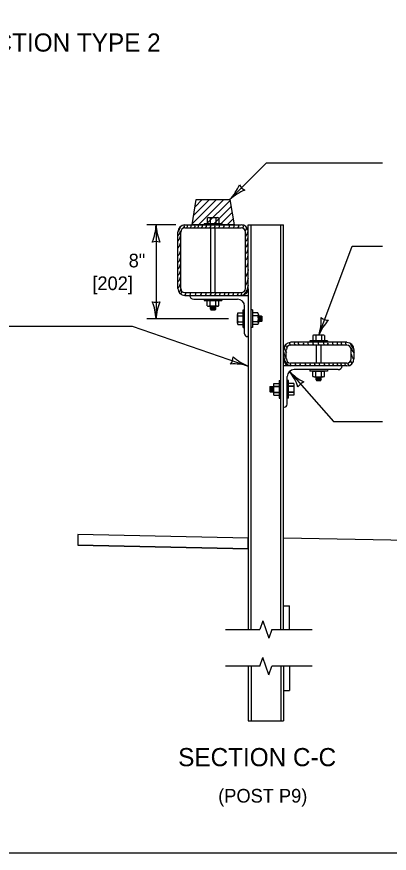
# Model space of a CAD drawing. Extents: x 49991.4 to 50021, y 49987.6 to 50011.4.
# Drawn here: x 50007.949 to 50009.589, y 49987.799 to 49991.481 of the extents above; entities that cross this region are included whole.
import ezdxf

# ---------------------------------------------------------------- set-up
doc = ezdxf.new("R2010")
doc.units = 0
for name, color, linetype in [('Level 1', 7, 'Continuous'), ('Level 2', 7, 'Continuous'), ('Level 3', 7, 'Continuous'), ('Level 4', 7, 'Continuous'), ('Level 6', 7, 'Continuous')]:
    doc.layers.add(name, color=color, linetype=linetype)

msp = doc.modelspace()

# ---------------------------------------------------------------- linework, layer by layer
at = {"layer": 'Level 1'}
for p, q in [((50008.7205, 49990.5649), (50008.739, 49990.6759)), ((50008.7212, 49990.5688), (50008.8285, 49990.6759)), ((50008.7274, 49990.6066), (50008.7969, 49990.6759)), ((50008.7338, 49990.6443), (50008.7655, 49990.6759)), ((50008.739, 49990.6759), (50008.8872, 49990.6759)), ((50008.7486, 49990.5649), (50008.8597, 49990.6759)), ((50008.7799, 49990.5649), (50008.8876, 49990.6726)), ((50008.8872, 49990.6759), (50008.9056, 49990.5649)), ((50008.8115, 49990.5649), (50008.8922, 49990.6457)), ((50008.8429, 49990.5649), (50008.8968, 49990.6188)), ((50008.8744, 49990.5649), (50008.9013, 49990.5917)), ((50008.6888, 49990.5643), (50008.6891, 49990.5649)), ((50008.689, 49990.5519), (50008.6891, 49990.552)), ((50008.6891, 49990.5649), (50008.9371, 49990.5649)), ((50008.6891, 49990.552), (50008.9371, 49990.552)), ((50008.9056, 49990.5649), (50008.7205, 49990.5649)), ((50008.8036, 49990.2665), (50008.8036, 49990.552)), ((50008.8063, 49990.552), (50008.8189, 49990.552)), ((50008.8226, 49990.2665), (50008.8226, 49990.552)), ((50008.9678, 49990.2835), (50008.9678, 49990.5649)), ((50008.9678, 49990.5649), (50009.1231, 49990.5649)), ((50008.9804, 49988.7839), (50008.9804, 49990.5649)), ((50009.1109, 49988.7839), (50009.1109, 49990.5649)), ((50009.1231, 49988.7839), (50009.1231, 49990.5649)), ((50008.6578, 49990.285), (50008.6578, 49990.5333)), ((50008.6704, 49990.285), (50008.6704, 49990.5333)), ((50008.9558, 49990.285), (50008.9558, 49990.5333)), ((50008.9678, 49990.285), (50008.9678, 49990.5333)), ((50008.9678, 49990.2835), (50008.9678, 49988.7839)), ((50008.6891, 49990.2665), (50008.9371, 49990.2665)), ((50008.6891, 49990.2543), (50008.9678, 49990.2543)), ((50008.728, 49990.2379), (50008.9208, 49990.2379)), ((50008.7743, 49990.2381), (50008.7743, 49990.2323)), ((50008.7743, 49990.2323), (50008.8519, 49990.2323)), ((50008.8386, 49990.2323), (50008.7874, 49990.2323)), ((50008.7874, 49990.2086), (50008.7874, 49990.2323)), ((50008.8322, 49990.207), (50008.7939, 49990.207)), ((50008.8001, 49990.2086), (50008.8001, 49990.2322)), ((50008.8013, 49990.1931), (50008.8013, 49990.207)), ((50008.8247, 49990.1931), (50008.8247, 49990.207)), ((50008.8259, 49990.2086), (50008.8259, 49990.2322)), ((50008.8386, 49990.2086), (50008.8386, 49990.2323)), ((50008.8519, 49990.2381), (50008.8519, 49990.2323)), ((50008.9514, 49990.0859), (50008.9514, 49990.2072)), ((50008.8247, 49990.1931), (50008.8013, 49990.1931)), ((50008.8013, 49990.1931), (50008.8036, 49990.1908)), ((50008.8036, 49990.1908), (50008.8224, 49990.1908)), ((50008.8047, 49990.2037), (50008.8212, 49990.2037)), ((50008.8047, 49990.2014), (50008.8212, 49990.2014)), ((50008.8047, 49990.199), (50008.8212, 49990.199)), ((50008.8047, 49990.1967), (50008.8212, 49990.1967)), ((50008.8247, 49990.1931), (50008.8224, 49990.1908)), ((50008.9206, 49990.1324), (50008.9206, 49990.1707)), ((50008.9222, 49990.1772), (50008.9459, 49990.1772)), ((50008.9459, 49990.1128), (50008.9459, 49990.1904)), ((50008.9459, 49990.1904), (50008.9522, 49990.1904)), ((50008.9459, 49990.1259), (50008.9459, 49990.1772)), ((50008.987, 49990.1904), (50008.9807, 49990.1904)), ((50008.987, 49990.1904), (50008.987, 49990.1128)), ((50008.987, 49990.1772), (50008.987, 49990.126)), ((50009.0107, 49990.1772), (50008.987, 49990.1772)), ((50009.0123, 49990.1708), (50009.0123, 49990.1325)), ((50008.9221, 49990.1645), (50008.9458, 49990.1645)), ((50008.9221, 49990.1386), (50008.9458, 49990.1386)), ((50009.0108, 49990.1645), (50008.9871, 49990.1645)), ((50009.0108, 49990.1387), (50008.9871, 49990.1387)), ((50009.0262, 49990.1633), (50009.0123, 49990.1633)), ((50009.0262, 49990.1399), (50009.0123, 49990.1399)), ((50009.0155, 49990.1433), (50009.0155, 49990.1598)), ((50009.0179, 49990.1433), (50009.0179, 49990.1598)), ((50009.0203, 49990.1433), (50009.0203, 49990.1598)), ((50009.0226, 49990.1433), (50009.0226, 49990.1598)), ((50009.0262, 49990.1633), (50009.0262, 49990.1399)), ((50009.0262, 49990.1633), (50009.0285, 49990.161)), ((50009.0262, 49990.1399), (50009.0285, 49990.1422)), ((50009.0285, 49990.1422), (50009.0285, 49990.161)), ((50008.9222, 49990.1259), (50008.9459, 49990.1259)), ((50008.9459, 49990.1128), (50008.9522, 49990.1128)), ((50008.987, 49990.1128), (50008.9807, 49990.1128)), ((50009.0107, 49990.126), (50008.987, 49990.126)), ((50008.9678, 49990.0733), (50008.964, 49990.0733)), ((50009.2524, 49990.0779), (50009.2524, 49990.0542)), ((50009.2972, 49990.0795), (50009.2589, 49990.0795)), ((50009.2651, 49990.0779), (50009.2651, 49990.0542)), ((50009.2909, 49990.0779), (50009.2909, 49990.0542)), ((50009.3036, 49990.0779), (50009.3036, 49990.0542)), ((50009.402, 49990.0479), (50009.1544, 49990.0479)), ((50009.402, 49990.0352), (50009.1544, 49990.0352)), ((50009.3168, 49990.0542), (50009.2392, 49990.0542)), ((50009.2392, 49990.0542), (50009.2392, 49990.0479)), ((50009.3036, 49990.0542), (50009.2524, 49990.0542)), ((50009.2684, 49989.9565), (50009.2684, 49990.0352)), ((50009.2848, 49990.0352), (50009.2722, 49990.0352)), ((50009.2885, 49989.9565), (50009.2885, 49990.0352)), ((50009.3168, 49990.0542), (50009.3168, 49990.0479)), ((50009.1231, 49989.975), (50009.1231, 49990.0165)), ((50009.1353, 49989.975), (50009.1353, 49990.0165)), ((50009.4215, 49989.975), (50009.4215, 49990.0165)), ((50009.4336, 49989.975), (50009.4336, 49990.0165)), ((50009.402, 49989.9565), (50009.1544, 49989.9565)), ((50009.402, 49989.9442), (50009.1231, 49989.9442)), ((50009.3635, 49989.9279), (50009.1701, 49989.9279)), ((50009.2392, 49989.9275), (50009.2392, 49989.9216)), ((50009.3168, 49989.9216), (50009.2392, 49989.9216)), ((50009.2524, 49989.9216), (50009.3036, 49989.9216)), ((50009.2524, 49989.8979), (50009.2524, 49989.9216)), ((50009.2651, 49989.8978), (50009.2651, 49989.9215)), ((50009.2909, 49989.8978), (50009.2909, 49989.9215)), ((50009.3036, 49989.8979), (50009.3036, 49989.9216)), ((50009.3168, 49989.9275), (50009.3168, 49989.9216)), ((50009.1041, 49989.8799), (50009.1041, 49989.8023)), ((50009.1041, 49989.8799), (50009.1104, 49989.8799)), ((50009.1452, 49989.8799), (50009.1389, 49989.8799)), ((50009.1397, 49989.7759), (50009.1397, 49989.8973)), ((50009.1452, 49989.8023), (50009.1452, 49989.8799)), ((50009.2589, 49989.8963), (50009.2972, 49989.8963)), ((50009.2662, 49989.8825), (50009.2662, 49989.8964)), ((50009.2896, 49989.8825), (50009.2662, 49989.8825)), ((50009.2662, 49989.8825), (50009.2685, 49989.8802)), ((50009.2685, 49989.8802), (50009.2873, 49989.8802)), ((50009.2696, 49989.8931), (50009.2861, 49989.8931)), ((50009.2696, 49989.8908), (50009.2861, 49989.8908)), ((50009.2696, 49989.8884), (50009.2861, 49989.8884)), ((50009.2696, 49989.8861), (50009.2861, 49989.8861)), ((50009.2896, 49989.8825), (50009.2873, 49989.8802)), ((50009.2896, 49989.8825), (50009.2896, 49989.8964)), ((50009.0649, 49989.8529), (50009.0625, 49989.8505)), ((50009.0625, 49989.8505), (50009.0625, 49989.8317)), ((50009.0648, 49989.8528), (50009.0787, 49989.8528)), ((50009.0648, 49989.8294), (50009.0648, 49989.8528)), ((50009.0684, 49989.8494), (50009.0684, 49989.8329)), ((50009.0708, 49989.8494), (50009.0708, 49989.8329)), ((50009.0731, 49989.8494), (50009.0731, 49989.8329)), ((50009.0755, 49989.8494), (50009.0755, 49989.8329)), ((50009.0787, 49989.8603), (50009.0787, 49989.822)), ((50009.0803, 49989.8667), (50009.104, 49989.8667)), ((50009.0803, 49989.854), (50009.104, 49989.854)), ((50009.104, 49989.8667), (50009.104, 49989.8155)), ((50009.1452, 49989.8154), (50009.1452, 49989.8666)), ((50009.1689, 49989.8666), (50009.1452, 49989.8666)), ((50009.1689, 49989.8539), (50009.1452, 49989.8539)), ((50009.1705, 49989.8218), (50009.1705, 49989.8602)), ((50009.0649, 49989.8294), (50009.0625, 49989.8317)), ((50009.0648, 49989.8294), (50009.0787, 49989.8294)), ((50009.0803, 49989.8282), (50009.104, 49989.8282)), ((50009.0803, 49989.8155), (50009.104, 49989.8155)), ((50009.1041, 49989.8023), (50009.1104, 49989.8023)), ((50009.1452, 49989.8023), (50009.1389, 49989.8023)), ((50009.1689, 49989.8281), (50009.1452, 49989.8281)), ((50009.1689, 49989.8154), (50009.1452, 49989.8154)), ((50008.9678, 49989.1864), (50008.2178, 49989.2014)), ((50008.9678, 49989.1395), (50008.9678, 49989.1864)), ((50009.8241, 49989.1724), (50009.1231, 49989.1864)), ((50008.2178, 49989.1545), (50008.9678, 49989.1395)), ((50008.9678, 49989.1395), (50008.2178, 49989.1545)), ((50009.1231, 49988.8881), (50009.1497, 49988.8881)), ((50009.1497, 49988.7839), (50009.1497, 49988.8881)), ((50008.9678, 49988.6223), (50008.9678, 49988.382)), ((50008.9804, 49988.6223), (50008.9804, 49988.382)), ((50009.1109, 49988.6223), (50009.1109, 49988.382)), ((50009.1231, 49988.6223), (50009.1231, 49988.382)), ((50009.1497, 49988.6223), (50009.1497, 49988.5152)), ((50009.1231, 49988.5152), (50009.1497, 49988.5152)), ((50008.9678, 49988.382), (50009.1231, 49988.382))]:
    msp.add_line(p, q, dxfattribs=at)
msp.add_lwpolyline([(49999.3835, 49998.9992), (50016.7501, 49998.9992), (50016.7501, 49987.7988), (49999.3835, 49987.7988)], close=True, dxfattribs=at)
for points in [[(50008.6578, 49990.5171), (50008.6636, 49990.5227), (50008.6673, 49990.5299), (50008.6704, 49990.5373)], [(50008.6589, 49990.5357), (50008.6643, 49990.5421), (50008.667, 49990.5479), (50008.6701, 49990.5568)], [(50008.6796, 49990.5496), (50008.6844, 49990.5536), (50008.6871, 49990.5574), (50008.6865, 49990.5637)], [(50008.697, 49990.552), (50008.701, 49990.5579), (50008.701, 49990.5649)], [(50008.7133, 49990.552), (50008.717, 49990.5579), (50008.717, 49990.5649)], [(50008.729, 49990.552), (50008.7335, 49990.5574), (50008.733, 49990.5637)], [(50008.7456, 49990.552), (50008.7491, 49990.5579), (50008.7491, 49990.5637)], [(50008.7624, 49990.552), (50008.7661, 49990.5579), (50008.7661, 49990.5637)], [(50008.7803, 49990.552), (50008.7835, 49990.5579), (50008.7835, 49990.5637)], [(50008.7988, 49990.552), (50008.8032, 49990.5574), (50008.8032, 49990.5637)], [(50008.8178, 49990.552), (50008.822, 49990.5579), (50008.8215, 49990.5637)], [(50008.8379, 49990.552), (50008.8416, 49990.5579), (50008.8411, 49990.5637)], [(50008.858, 49990.552), (50008.8617, 49990.5579), (50008.8617, 49990.5637)], [(50008.8819, 49990.552), (50008.8853, 49990.5579), (50008.8853, 49990.5649)], [(50008.9023, 49990.552), (50008.9054, 49990.5579), (50008.9054, 49990.5637)], [(50008.9224, 49990.552), (50008.9266, 49990.5579), (50008.9262, 49990.5637)], [(50008.9429, 49990.5511), (50008.9467, 49990.5568), (50008.9462, 49990.5632)], [(50008.9558, 49990.5401), (50008.96, 49990.5459), (50008.96, 49990.552)], [(50008.9568, 49990.5155), (50008.962, 49990.5221), (50008.9653, 49990.5279), (50008.9678, 49990.5373)], [(50008.6588, 49990.4941), (50008.6642, 49990.5008), (50008.6669, 49990.5067), (50008.67, 49990.5155)], [(50008.9562, 49990.491), (50008.9616, 49990.4968), (50008.964, 49990.503), (50008.9674, 49990.5114)], [(50008.6584, 49990.4628), (50008.6636, 49990.4693), (50008.6663, 49990.4751), (50008.6694, 49990.4839)], [(50008.9562, 49990.4645), (50008.9616, 49990.4709), (50008.964, 49990.4777), (50008.9674, 49990.4862)], [(50008.6584, 49990.4287), (50008.6636, 49990.4348), (50008.6663, 49990.4407), (50008.6694, 49990.4498)], [(50008.9562, 49990.4369), (50008.9616, 49990.4434), (50008.964, 49990.4491), (50008.9674, 49990.458)], [(50008.9562, 49990.4095), (50008.9616, 49990.4153), (50008.964, 49990.4219), (50008.9674, 49990.4301)], [(50008.6584, 49990.399), (50008.6636, 49990.4052), (50008.6669, 49990.4112), (50008.6694, 49990.4202)], [(50008.6584, 49990.3705), (50008.6636, 49990.3763), (50008.6669, 49990.3826), (50008.6694, 49990.3915)], [(50008.9562, 49990.3773), (50008.9616, 49990.3831), (50008.964, 49990.3889), (50008.9674, 49990.3983)], [(50008.6584, 49990.3415), (50008.6636, 49990.3479), (50008.6669, 49990.3537), (50008.6694, 49990.3626)], [(50008.9678, 49990.3683), (50008.9656, 49990.3571), (50008.962, 49990.3466), (50008.9562, 49990.3361)], [(50008.6584, 49990.3135), (50008.6636, 49990.3197), (50008.6669, 49990.3255), (50008.6694, 49990.3346)], [(50008.9674, 49990.3308), (50008.9653, 49990.3197), (50008.9616, 49990.3091), (50008.9558, 49990.2986)], [(50008.6584, 49990.2866), (50008.6636, 49990.2927), (50008.6669, 49990.2986), (50008.6694, 49990.3071)], [(50008.6704, 49990.2839), (50008.6689, 49990.276), (50008.6663, 49990.2712), (50008.6621, 49990.2696)], [(50008.9678, 49990.2996), (50008.9653, 49990.289), (50008.9616, 49990.278), (50008.9562, 49990.2675), (50008.9477, 49990.2569)], [(50008.6714, 49990.2607), (50008.6757, 49990.2665), (50008.6754, 49990.2723)], [(50008.6891, 49990.2543), (50008.6932, 49990.2607), (50008.6925, 49990.2665)], [(50008.7101, 49990.2543), (50008.7138, 49990.2601), (50008.7133, 49990.2659)], [(50008.7335, 49990.2543), (50008.7371, 49990.2601), (50008.7365, 49990.2659)], [(50008.7576, 49990.2543), (50008.762, 49990.2607), (50008.762, 49990.2665)], [(50008.7797, 49990.2543), (50008.7831, 49990.2607), (50008.7831, 49990.2665)], [(50008.8004, 49990.2543), (50008.8047, 49990.2607), (50008.8042, 49990.2665)], [(50008.821, 49990.2549), (50008.8247, 49990.2607), (50008.8247, 49990.2665)], [(50008.8411, 49990.2549), (50008.8448, 49990.2607), (50008.8448, 49990.2669)], [(50008.8612, 49990.2543), (50008.8648, 49990.2607), (50008.8642, 49990.2665)], [(50008.8792, 49990.2543), (50008.8829, 49990.2607), (50008.8823, 49990.2665)], [(50008.8997, 49990.2543), (50008.9035, 49990.2607), (50008.9035, 49990.2665)], [(50008.9198, 49990.2543), (50008.9236, 49990.2601), (50008.9232, 49990.2665)], [(50008.9351, 49990.2543), (50008.9395, 49990.2601), (50008.9387, 49990.2665)], [(50009.1254, 49990.0263), (50009.1285, 49990.0155), (50009.1333, 49990.0059), (50009.1364, 49990.0019)], [(50009.1381, 49990.0266), (50009.1336, 49990.0325), (50009.1343, 49990.0389)], [(50009.1548, 49990.0345), (50009.1513, 49990.041), (50009.1513, 49990.0467)], [(50009.1754, 49990.0361), (50009.1718, 49990.0419), (50009.1724, 49990.0467)], [(50009.1929, 49990.0361), (50009.1898, 49990.0419), (50009.1898, 49990.0467)], [(50009.2151, 49990.0352), (50009.2109, 49990.041), (50009.2119, 49990.0462)], [(50009.2352, 49990.0352), (50009.2314, 49990.041), (50009.2314, 49990.0462)], [(50009.2569, 49990.0361), (50009.2531, 49990.0419), (50009.2538, 49990.0467)], [(50009.2804, 49990.0352), (50009.277, 49990.041), (50009.2774, 49990.0462)], [(50009.3032, 49990.0352), (50009.3001, 49990.041), (50009.3001, 49990.0462)], [(50009.323, 49990.0352), (50009.3187, 49990.041), (50009.3192, 49990.0462)], [(50009.3438, 49990.0352), (50009.3404, 49990.041), (50009.3404, 49990.0462)], [(50009.3639, 49990.0345), (50009.3604, 49990.041), (50009.3604, 49990.0462)], [(50009.3826, 49990.0352), (50009.3782, 49990.041), (50009.3788, 49990.0462)], [(50009.401, 49990.0352), (50009.3968, 49990.041), (50009.3979, 49990.0462)], [(50009.4164, 49990.0436), (50009.4195, 49990.0361), (50009.4232, 49990.0294), (50009.4269, 49990.0256), (50009.4327, 49990.0208)], [(50009.42, 49990.0219), (50009.4238, 49990.0151), (50009.4276, 49990.0076), (50009.4336, 49990.0001)], [(50009.1231, 49990.0072), (50009.1264, 49989.9956), (50009.1306, 49989.9855), (50009.1353, 49989.977)], [(50009.1231, 49989.9871), (50009.1259, 49989.975), (50009.1296, 49989.9655), (50009.1353, 49989.9575)], [(50009.4333, 49989.9733), (50009.4276, 49989.9797), (50009.4248, 49989.9855), (50009.4221, 49989.9939)], [(50009.1353, 49989.9575), (50009.1432, 49989.9463)], [(50009.158, 49989.9442), (50009.1544, 49989.95), (50009.1548, 49989.9555)], [(50009.1796, 49989.9449), (50009.1759, 49989.9507), (50009.1759, 49989.9559)], [(50009.201, 49989.9449), (50009.1967, 49989.9507), (50009.1972, 49989.9559)], [(50009.2236, 49989.9449), (50009.2198, 49989.9507), (50009.2198, 49989.9559)], [(50009.2447, 49989.9449), (50009.2409, 49989.9507), (50009.2416, 49989.9559)], [(50009.2647, 49989.9449), (50009.261, 49989.9507), (50009.261, 49989.9559)], [(50009.2852, 49989.9449), (50009.2822, 49989.9507), (50009.2822, 49989.9559)], [(50009.3076, 49989.9449), (50009.3032, 49989.9507), (50009.3032, 49989.9559)], [(50009.327, 49989.9442), (50009.324, 49989.95), (50009.324, 49989.9555)], [(50009.3466, 49989.9449), (50009.3424, 49989.9507), (50009.3428, 49989.9559)], [(50009.3647, 49989.9449), (50009.3608, 49989.9507), (50009.3608, 49989.9559)], [(50009.381, 49989.9449), (50009.3768, 49989.9507), (50009.3768, 49989.9559)], [(50009.3979, 49989.9442), (50009.3942, 49989.95), (50009.3942, 49989.9559)], [(50009.4123, 49989.9463), (50009.4079, 49989.9521), (50009.4085, 49989.9575)], [(50009.4184, 49989.9655), (50009.4195, 49989.9616), (50009.4221, 49989.9569), (50009.4259, 49989.9555)], [(50008.2178, 49989.2014), (50008.2178, 49989.1545)]]:
    msp.add_lwpolyline(points, dxfattribs=at)
for centre, radius, start, end in [((50008.6888, 49990.5333), 0.031, 90, 180), ((50008.689, 49990.5333), 0.0186, 90, 180), ((50008.9371, 49990.5339), 0.031, 8.2189, 90), ((50008.9371, 49990.5334), 0.0186, 0, 90), ((50008.6891, 49990.2853), 0.031, 180, 270), ((50008.6891, 49990.2851), 0.0186, 180, 270), ((50008.9368, 49990.2851), 0.0186, 270, 0), ((50008.9368, 49990.2853), 0.031, 270, 356.5777), ((50008.728, 49990.2566), 0.0186, 187.6623, 270), ((50008.9207, 49990.2069), 0.031, 0, 90), ((50008.9641, 49990.0855), 0.0124, 180, 270), ((50009.1543, 49990.0162), 0.031, 90, 180), ((50009.1543, 49990.0162), 0.0186, 90, 180), ((50009.4024, 49990.0162), 0.031, 0, 90), ((50009.4024, 49990.0162), 0.0186, 0, 90), ((50009.1543, 49989.9748), 0.031, 180, 270), ((50009.1543, 49989.9748), 0.0186, 180, 270), ((50009.4024, 49989.9748), 0.0186, 270, 0), ((50009.4024, 49989.9748), 0.031, 270, 0), ((50009.1704, 49989.8967), 0.031, 90, 180), ((50009.3631, 49989.9463), 0.0186, 270, 352.3377), ((50009.127, 49989.7753), 0.0124, 254.6726, 0)]:
    msp.add_arc(centre, radius, start, end, dxfattribs=at)
for centre, major_axis, start_param, end_param in [((50008.7938, 49990.219), (-0.0128, 0), 1.047198, 2.084746), ((50008.813, 49990.255), (-0.0512, 0), 1.315951, 1.825641), ((50008.8322, 49990.219), (-0.0128, 0), 1.056847, 2.094396), ((50008.9326, 49990.1708), (0, 0.0128), 1.047198, 2.084746), ((50009.0003, 49990.1708), (0, -0.0128), 1.056847, 2.094396), ((50008.9326, 49990.1323), (0, 0.0128), 1.056847, 2.094396), ((50008.9685, 49990.1516), (0, 0.0512), 1.315951, 1.825641), ((50009.0003, 49990.1324), (0, -0.0128), 1.047198, 2.084746), ((50008.9644, 49990.1516), (0, -0.0512), 1.315951, 1.825641), ((50009.2588, 49990.0675), (-0.0128, 0), 4.198439, 5.235988), ((50009.278, 49990.0315), (-0.0512, 0), 4.457545, 4.967234), ((50009.2972, 49990.0675), (-0.0128, 0), 4.188789, 5.226338), ((50009.2588, 49989.9083), (0.0128, 0), 4.188789, 5.226338), ((50009.278, 49989.9442), (0.0512, 0), 4.457545, 4.967234), ((50009.2972, 49989.9083), (0.0128, 0), 4.198439, 5.235988), ((50009.0907, 49989.8603), (0, -0.0128), 4.188789, 5.226338), ((50009.1267, 49989.8411), (0, -0.0512), 4.457545, 4.967234), ((50009.1585, 49989.8602), (0, 0.0128), 4.198439, 5.235988), ((50009.1225, 49989.841), (0, 0.0512), 4.457545, 4.967234), ((50009.0907, 49989.8219), (0, -0.0128), 4.198439, 5.235988), ((50009.1585, 49989.8218), (0, 0.0128), 4.188789, 5.226338)]:
    msp.add_ellipse(centre, major_axis=major_axis, ratio=0.93686, start_param=start_param, end_param=end_param, dxfattribs=at)
at = {"layer": 'Level 3'}
for p, q in [((50008.8872, 49990.6759), (50009.0485, 49990.8385)), ((50009.0485, 49990.8385), (50009.5585, 49990.8385)), ((50008.6491, 49990.5649), (50008.5221, 49990.5649)), ((50008.5621, 49990.5649), (50008.5621, 49990.1507)), ((50009.2784, 49990.0795), (50009.4254, 49990.471)), ((50009.4254, 49990.471), (50009.5585, 49990.471)), ((50008.8806, 49990.1507), (50008.5221, 49990.1507)), ((50007.8581, 49990.1185), (50008.4571, 49990.1185)), ((50008.4571, 49990.1185), (50008.9678, 49989.9434)), ((50009.1494, 49989.9195), (50009.3425, 49989.6986)), ((50009.3425, 49989.6986), (50009.5585, 49989.6986))]:
    msp.add_line(p, q, dxfattribs=at)
for centre, radius, start, end in [((50008.7139, 49990.8316), 0.233, 318.061, 337.3109), ((50008.9775, 49990.7669), 0.0548, 207.3726, 243.0949), ((50009.0385, 49990.513), 0.2223, 112.6897, 132.8733), ((50008.34, 49990.5741), 0.2223, 337.456, 357.6395), ((50008.7948, 49990.5764), 0.233, 182.8273, 202.0772), ((50008.5621, 49990.4367), 0.0548, 72.1388, 107.8612), ((50008.5621, 49990.2789), 0.0548, 252.1388, 287.8612), ((50008.3294, 49990.1392), 0.233, 2.8273, 22.0772), ((50008.7842, 49990.1415), 0.2223, 157.456, 177.6395), ((50009.0565, 49990.1505), 0.233, 342.2453, 1.4951), ((50009.4831, 49989.9928), 0.2223, 136.874, 157.0575), ((50009.3235, 49990.1995), 0.0548, 231.5568, 267.2792), ((50008.8465, 49989.985), 0.0548, 323.2166, 358.939), ((50008.9032, 49989.7196), 0.233, 73.9051, 93.1549), ((50009.0485, 49990.1506), 0.2223, 228.5338, 248.7173), ((50008.9761, 49989.7801), 0.2223, 18.6248, 38.8083), ((50009.317, 49990.0813), 0.233, 223.9961, 243.246), ((50009.2338, 49989.823), 0.0548, 113.3076, 149.03)]:
    msp.add_arc(centre, radius, start, end, dxfattribs=at)
at = {"layer": 'Level 4'}
for p, q in [((50008.7871, 49990.595), (50008.7871, 49990.5713)), ((50008.7935, 49990.5966), (50008.8318, 49990.5966)), ((50008.7998, 49990.595), (50008.7998, 49990.5714)), ((50008.8256, 49990.595), (50008.8256, 49990.5714)), ((50008.8383, 49990.595), (50008.8383, 49990.5713)), ((50008.774, 49990.5713), (50008.8516, 49990.5713)), ((50008.774, 49990.5713), (50008.774, 49990.5649)), ((50008.7871, 49990.5713), (50008.8383, 49990.5713)), ((50008.8516, 49990.5713), (50008.8516, 49990.5649)), ((50009.0796, 49989.8554), (50009.104, 49989.8554)), ((50009.1696, 49989.8554), (50009.1452, 49989.8554)), ((50009.0796, 49989.8268), (50009.104, 49989.8268)), ((50009.1696, 49989.8267), (50009.1452, 49989.8267))]:
    msp.add_line(p, q, dxfattribs=at)
for centre, major_axis, start_param, end_param in [((50008.7935, 49990.5846), (0.0128, 0), 1.056847, 2.094396), ((50008.8127, 49990.5486), (0.0512, 0), 1.315951, 1.825641), ((50008.8319, 49990.5846), (0.0128, 0), 1.047198, 2.084746)]:
    msp.add_ellipse(centre, major_axis=major_axis, ratio=0.93686, start_param=start_param, end_param=end_param, dxfattribs=at)
at = {"layer": 'Level 6'}
for p, q in [((50009.0321, 49988.8218), (50009.0187, 49988.7839)), ((50009.0321, 49988.8218), (50009.0455, 49988.7839)), ((50008.8678, 49988.7839), (50009.0187, 49988.7839)), ((50009.0455, 49988.7839), (50009.059, 49988.746)), ((50009.0724, 49988.7839), (50009.059, 49988.746)), ((50009.0724, 49988.7839), (50009.2497, 49988.7839)), ((50009.0186, 49988.6223), (50009.032, 49988.6602)), ((50009.0455, 49988.6223), (50009.032, 49988.6602)), ((50009.0186, 49988.6223), (50008.8678, 49988.6223)), ((50009.0589, 49988.5844), (50009.0455, 49988.6223)), ((50009.0589, 49988.5844), (50009.0723, 49988.6223)), ((50009.2497, 49988.6223), (50009.0723, 49988.6223))]:
    msp.add_line(p, q, dxfattribs=at)

# ---------------------------------------------------------------- texts
at = {"layer": 'Level 2'}
for s, height, p in [('BOX BEAM - BRIDGE APPROACH SECTION TYPE 2', 0.08, (50005.9846, 49991.3275)), ('8"', 0.06, (50008.4414, 49990.3778)), ('[202]', 0.06, (50008.2816, 49990.2778)), ('SECTION C-C', 0.08, (50008.6594, 49988.182)), ('(POST P9)', 0.06, (50008.8357, 49988.022))]:
    msp.add_text(s, height=height, dxfattribs=at).set_placement(p)

doc.saveas('drawing.dxf')
